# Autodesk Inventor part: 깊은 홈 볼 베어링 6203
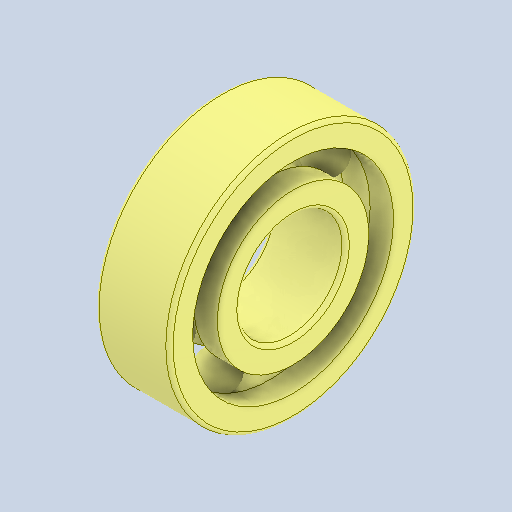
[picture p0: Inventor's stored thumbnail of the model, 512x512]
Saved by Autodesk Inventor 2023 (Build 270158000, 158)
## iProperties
Created: 2025-03
Part Number: 깊은 홈 볼 베어링 6203
Material: 강철, 연강
Description: 깊은 그루브 볼 베어링
Document SubType Name: Modeling
Designer: user
Density: 7.85 g/cm^3
Appearance: 기본값
Author: jhkim
Sending System: Autodesk Inventor 2025
Preprocessor: ST-DEVELOPER v20
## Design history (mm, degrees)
feature "Solid1"
feature "Solid1:1"
feature "Solid1:2"
feature "Solid1:3"
feature "Solid1:4"
feature "Solid1:5"
feature "Solid1:6"
feature "Solid1:7"
feature "Solid1:8"
node "솔리드1"
node "솔리드2"
node "솔리드3"
node "솔리드4"
node "솔리드5"
node "솔리드6"
node "솔리드7"
node "솔리드8"
node "솔리드9"
